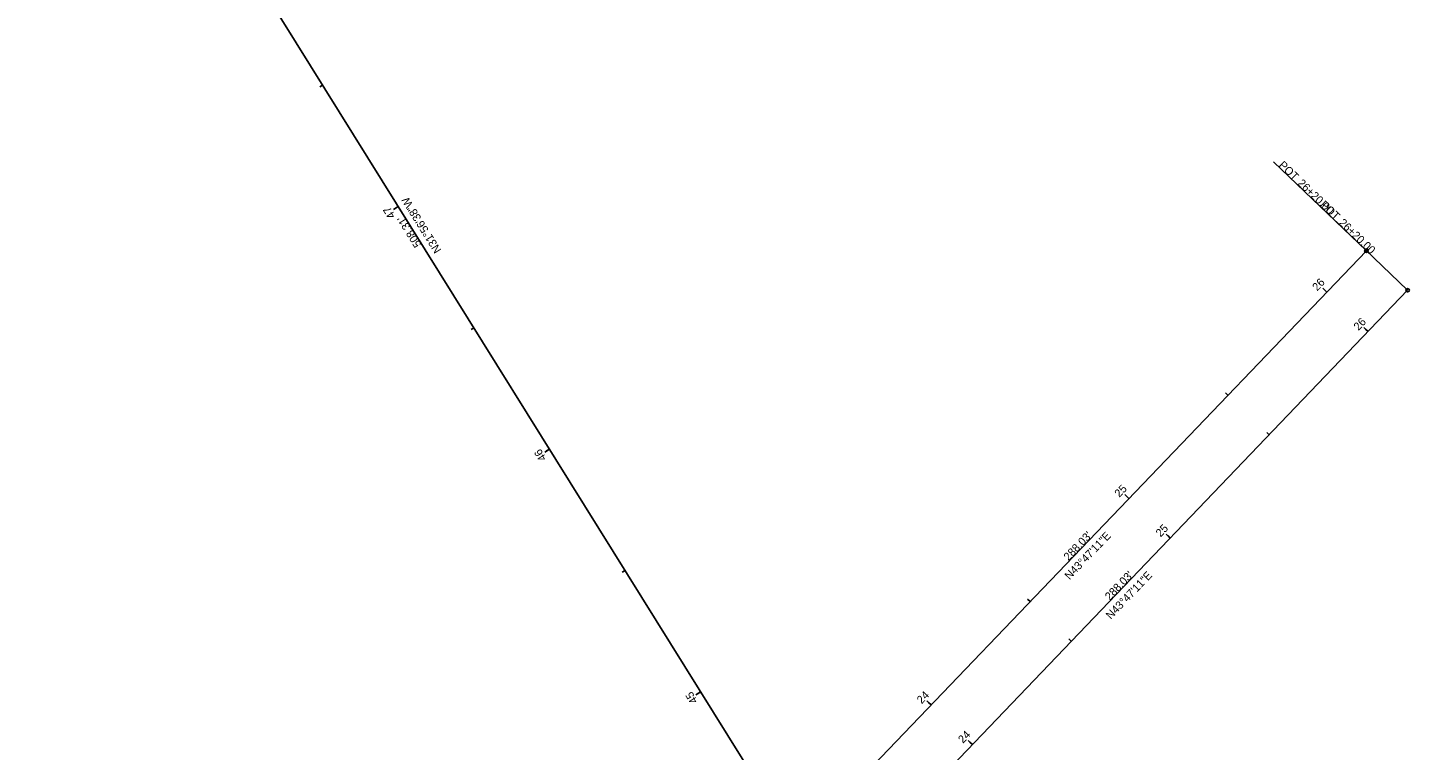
# Model space of a CAD drawing. Extents: x 1363001 to 1363920, y 487582 to 489802.
# Drawn here: x 1363355.8 to 1363839, y 488934.2 to 489186.9 of the extents above; entities that cross this region are included whole.
import ezdxf

# ---------------------------------------------------------------- set-up
doc = ezdxf.new("R2010")
doc.units = 0
for name, color, linetype in [('BR_X_SV_Beam_Seat', 7, 'Continuous'), ('BR_X_SV_Bottom_of_Beam_Text', 7, 'Continuous'), ('BR_X_SV_Deck_Top', 7, 'Continuous'), ('BR_X_SV_Deck_Top_Text', 7, 'Continuous'), ('BR_X_SV_Shot_Marker', 7, 'Continuous'), ('DR_X_Cells', 7, 'Continuous'), ('PV_X_COP', 7, 'Continuous'), ('PV_X_Curb', 7, 'Continuous'), ('PV_X_EOP', 7, 'Continuous'), ('PV_X_Shoulder_Aggregate', 7, 'Continuous'), ('RD_X_Cells', 7, 'Continuous'), ('RD_X_Concrete_Pad', 7, 'Continuous'), ('RD_X_GR_Lt', 7, 'Continuous'), ('RD_X_GR_Rt', 7, 'Continuous'), ('SG_X_Interconnect_Cable', 7, 'Continuous'), ('SG_X_PullBox', 7, 'Continuous'), ('SN_X_Public', 7, 'Continuous'), ('SV_P_Aerial_Targets', 7, 'Continuous'), ('SV_P_Mon_Cells_Set', 7, 'Continuous'), ('SV_X_Break_Lines', 7, 'Continuous'), ('SV_X_Mon_Cells_Found', 7, 'Continuous'), ('SV_X_Random_Point', 7, 'Continuous'), ('SV_X_Text_Comment', 7, 'Continuous'), ('SV_X_Text_Name', 7, 'Continuous'), ('UT_X_Electric_Cells', 7, 'Continuous'), ('UT_X_Misc_Cells', 7, 'Continuous'), ('UT_X_Water', 7, 'Continuous')]:
    doc.layers.add(name, color=color, linetype=linetype)

msp = doc.modelspace()

# ---------------------------------------------------------------- linework, layer by layer
at = {"layer": 'BR_X_SV_Bottom_of_Beam_Text'}
msp.add_line((1363824, 489108.89), (1363791.51, 489140.03), dxfattribs=at)
msp.add_circle((1363824, 489108.89), 0.6, dxfattribs=at)
at = {"layer": 'BR_X_SV_Deck_Top'}
for p, q in [((1363824.6, 489080.62), (1363823.15, 489082)), ((1363790, 489044.52), (1363789.13, 489045.35)), ((1363755.4, 489008.42), (1363753.96, 489009.81)), ((1363720.8, 488972.33), (1363719.94, 488973.16)), ((1363686.2, 488936.23), (1363684.76, 488937.61))]:
    msp.add_line(p, q, dxfattribs=at)
at = {"layer": 'BR_X_SV_Deck_Top_Text'}
msp.add_line((1363639.13, 488887.12), (1363838.44, 489095.06), dxfattribs=at)
at = {"layer": 'BR_X_SV_Shot_Marker'}
for p, q in [((1363458.94, 489166.8), (1363457.92, 489166.16)), ((1363485.39, 489124.37), (1363483.7, 489123.31)), ((1363810.16, 489094.45), (1363808.72, 489095.84)), ((1363511.85, 489081.94), (1363510.83, 489081.31)), ((1363775.56, 489058.36), (1363774.69, 489059.19)), ((1363538.3, 489039.51), (1363536.6, 489038.45)), ((1363740.96, 489022.26), (1363739.52, 489023.65)), ((1363564.76, 488997.08), (1363563.74, 488996.45)), ((1363706.36, 488986.17), (1363705.5, 488987)), ((1363591.21, 488954.66), (1363589.51, 488953.6)), ((1363671.76, 488950.07), (1363670.32, 488951.45))]:
    msp.add_line(p, q, dxfattribs=at)
at = {"layer": 'PV_X_COP'}
for p, q in [((1363824.6, 489080.62), (1363823.73, 489081.45)), ((1363755.4, 489008.42), (1363753.96, 489009.81)), ((1363686.2, 488936.23), (1363685.34, 488937.06))]:
    msp.add_line(p, q, dxfattribs=at)
at = {"layer": 'PV_X_Curb'}
msp.add_line((1363824, 489108.89), (1363791.51, 489140.03), dxfattribs=at)
msp.add_circle((1363824, 489108.89), 0.6, dxfattribs=at)
at = {"layer": 'PV_X_Shoulder_Aggregate'}
msp.add_line((1363838.44, 489095.06), (1363805.95, 489126.19), dxfattribs=at)
msp.add_circle((1363838.44, 489095.06), 0.6, dxfattribs=at)
at = {"layer": 'RD_X_Concrete_Pad'}
msp.add_line((1363838.44, 489095.06), (1363805.95, 489126.19), dxfattribs=at)
msp.add_circle((1363838.44, 489095.06), 0.6, dxfattribs=at)
at = {"layer": 'RD_X_GR_Rt'}
for p, q in [((1363740.96, 489022.26), (1363740.1, 489023.09)), ((1363591.21, 488954.66), (1363590.19, 488954.02))]:
    msp.add_line(p, q, dxfattribs=at)
at = {"layer": 'SG_X_PullBox'}
for p, q in [((1363485.39, 489124.37), (1363484.37, 489123.73)), ((1363810.16, 489094.45), (1363809.29, 489095.29)), ((1363538.3, 489039.51), (1363537.28, 489038.88)), ((1363740.96, 489022.26), (1363739.52, 489023.65)), ((1363591.21, 488954.66), (1363589.51, 488953.6)), ((1363671.76, 488950.07), (1363670.9, 488950.9))]:
    msp.add_line(p, q, dxfattribs=at)
at = {"layer": 'SN_X_Public'}
msp.add_line((1363838.44, 489095.06), (1363805.95, 489126.19), dxfattribs=at)
msp.add_circle((1363838.44, 489095.06), 0.6, dxfattribs=at)
at = {"layer": 'SV_X_Text_Comment'}
for q in [(1363355.75, 489332.29), (1363824, 489108.89)]:
    msp.add_line((1363624.69, 488900.96), q, dxfattribs=at)
at = {"layer": 'SV_X_Text_Name'}
for p, q in [((1363823.33, 489108.23), (1363824.67, 489109.56)), ((1363823.33, 489109.56), (1363824.67, 489108.23))]:
    msp.add_line(p, q, dxfattribs=at)
at = {"layer": 'UT_X_Misc_Cells'}
msp.add_line((1363755.4, 489008.42), (1363754.53, 489009.25), dxfattribs=at)
at = {"layer": 'UT_X_Water'}
msp.add_line((1363824, 489108.89), (1363791.51, 489140.03), dxfattribs=at)
msp.add_circle((1363824, 489108.89), 0.6, dxfattribs=at)

# ---------------------------------------------------------------- texts
at = {"layer": 'BR_X_SV_Beam_Seat'}
for s, rotation, p in [('N31°56\'38"W', 121.9439, (1363500.57, 489109.1)), ('N43°47\'11"E', 46.2136, (1363720.17, 488993.64))]:
    msp.add_text(s, height=2.8, rotation=rotation, dxfattribs=at).set_placement(p)
at = {"layer": 'BR_X_SV_Bottom_of_Beam_Text'}
for s, p in [('POT', (1363793.14, 489138.54)), ('26+20.00', (1363799.73, 489132.22))]:
    msp.add_text(s, height=2.8, rotation=316.2136, dxfattribs=at).set_placement(p)
at = {"layer": 'BR_X_SV_Deck_Top'}
for s, p in [('26', (1363821.24, 489080.79)), ('25', (1363752.03, 489008.59)), ('24', (1363682.91, 488936.41))]:
    msp.add_text(s, height=2.8, rotation=46.2136, dxfattribs=at).set_placement(p)
at = {"layer": 'BR_X_SV_Shot_Marker'}
for s, rotation, p in [('47', 121.9439, (1363484.46, 489121.14)), ('26', 46.2136, (1363806.8, 489094.63)), ('46', 121.9439, (1363537.3, 489036.3)), ('25', 46.2136, (1363737.6, 489022.43)), ('45', 121.9439, (1363590.22, 488951.44)), ('24', 46.2136, (1363668.47, 488950.25))]:
    msp.add_text(s, height=2.8, rotation=rotation, dxfattribs=at).set_placement(p)
at = {"layer": 'DR_X_Cells'}
for s, rotation, p in [("508.31'", 121.9439, (1363493.61, 489111.1)), ("288.03'", 46.2136, (1363719.82, 489000.28))]:
    msp.add_text(s, height=2.8, rotation=rotation, dxfattribs=at).set_placement(p)
at = {"layer": 'PV_X_COP'}
msp.add_text('25', height=2.8, rotation=46.2136, dxfattribs=at).set_placement((1363752.03, 489008.59))
at = {"layer": 'PV_X_Curb'}
for s, p in [('POT', (1363793.14, 489138.54)), ('26+20.00', (1363799.73, 489132.22))]:
    msp.add_text(s, height=2.8, rotation=316.2136, dxfattribs=at).set_placement(p)
at = {"layer": 'PV_X_EOP'}
msp.add_text('N43°47\'11"E', height=2.8, rotation=46.2136, dxfattribs=at).set_placement((1363734.61, 488979.8))
at = {"layer": 'PV_X_Shoulder_Aggregate'}
for s, p in [('POT', (1363807.58, 489124.7)), ('26+20.00', (1363814.17, 489118.38))]:
    msp.add_text(s, height=2.8, rotation=316.2136, dxfattribs=at).set_placement(p)
at = {"layer": 'RD_X_Cells'}
msp.add_text('N43°47\'11"E', height=2.8, rotation=46.2136, dxfattribs=at).set_placement((1363734.61, 488979.8))
at = {"layer": 'RD_X_Concrete_Pad'}
for s, p in [('POT', (1363807.58, 489124.7)), ('26+20.00', (1363814.17, 489118.38))]:
    msp.add_text(s, height=2.8, rotation=316.2136, dxfattribs=at).set_placement(p)
at = {"layer": 'RD_X_GR_Lt'}
for s, rotation, p in [("508.31'", 121.9439, (1363493.61, 489111.1)), ("288.03'", 46.2136, (1363719.82, 489000.28))]:
    msp.add_text(s, height=2.8, rotation=rotation, dxfattribs=at).set_placement(p)
at = {"layer": 'SG_X_Interconnect_Cable'}
for s, rotation, p in [('N31°56\'38"W', 121.9439, (1363500.57, 489109.1)), ('N43°47\'11"E', 46.2136, (1363720.17, 488993.64))]:
    msp.add_text(s, height=2.8, rotation=rotation, dxfattribs=at).set_placement(p)
at = {"layer": 'SG_X_PullBox'}
for s, rotation, p in [('25', 46.2136, (1363737.6, 489022.43)), ('45', 121.9439, (1363590.22, 488951.44))]:
    msp.add_text(s, height=2.8, rotation=rotation, dxfattribs=at).set_placement(p)
at = {"layer": 'SN_X_Public'}
for s, p in [('POT', (1363807.58, 489124.7)), ('26+20.00', (1363814.17, 489118.38))]:
    msp.add_text(s, height=2.8, rotation=316.2136, dxfattribs=at).set_placement(p)
at = {"layer": 'SV_P_Aerial_Targets'}
msp.add_text("288.03'", height=2.8, rotation=46.2136, dxfattribs=at).set_placement((1363734.26, 488986.44))
at = {"layer": 'SV_P_Mon_Cells_Set'}
msp.add_text('N43°47\'11"E', height=2.8, rotation=46.2136, dxfattribs=at).set_placement((1363734.61, 488979.8))
at = {"layer": 'SV_X_Break_Lines'}
for s, rotation, p in [("508.31'", 121.9439, (1363493.61, 489111.1)), ("288.03'", 46.2136, (1363719.82, 489000.28))]:
    msp.add_text(s, height=2.8, rotation=rotation, dxfattribs=at).set_placement(p)
at = {"layer": 'SV_X_Mon_Cells_Found'}
msp.add_text("288.03'", height=2.8, rotation=46.2136, dxfattribs=at).set_placement((1363734.26, 488986.44))
at = {"layer": 'SV_X_Random_Point'}
msp.add_text("288.03'", height=2.8, rotation=46.2136, dxfattribs=at).set_placement((1363734.26, 488986.44))
at = {"layer": 'UT_X_Electric_Cells'}
for s, rotation, p in [('N31°56\'38"W', 121.9439, (1363500.57, 489109.1)), ('N43°47\'11"E', 46.2136, (1363720.17, 488993.64))]:
    msp.add_text(s, height=2.8, rotation=rotation, dxfattribs=at).set_placement(p)
at = {"layer": 'UT_X_Water'}
for s, p in [('POT', (1363793.14, 489138.54)), ('26+20.00', (1363799.73, 489132.22))]:
    msp.add_text(s, height=2.8, rotation=316.2136, dxfattribs=at).set_placement(p)

doc.saveas('drawing.dxf')
